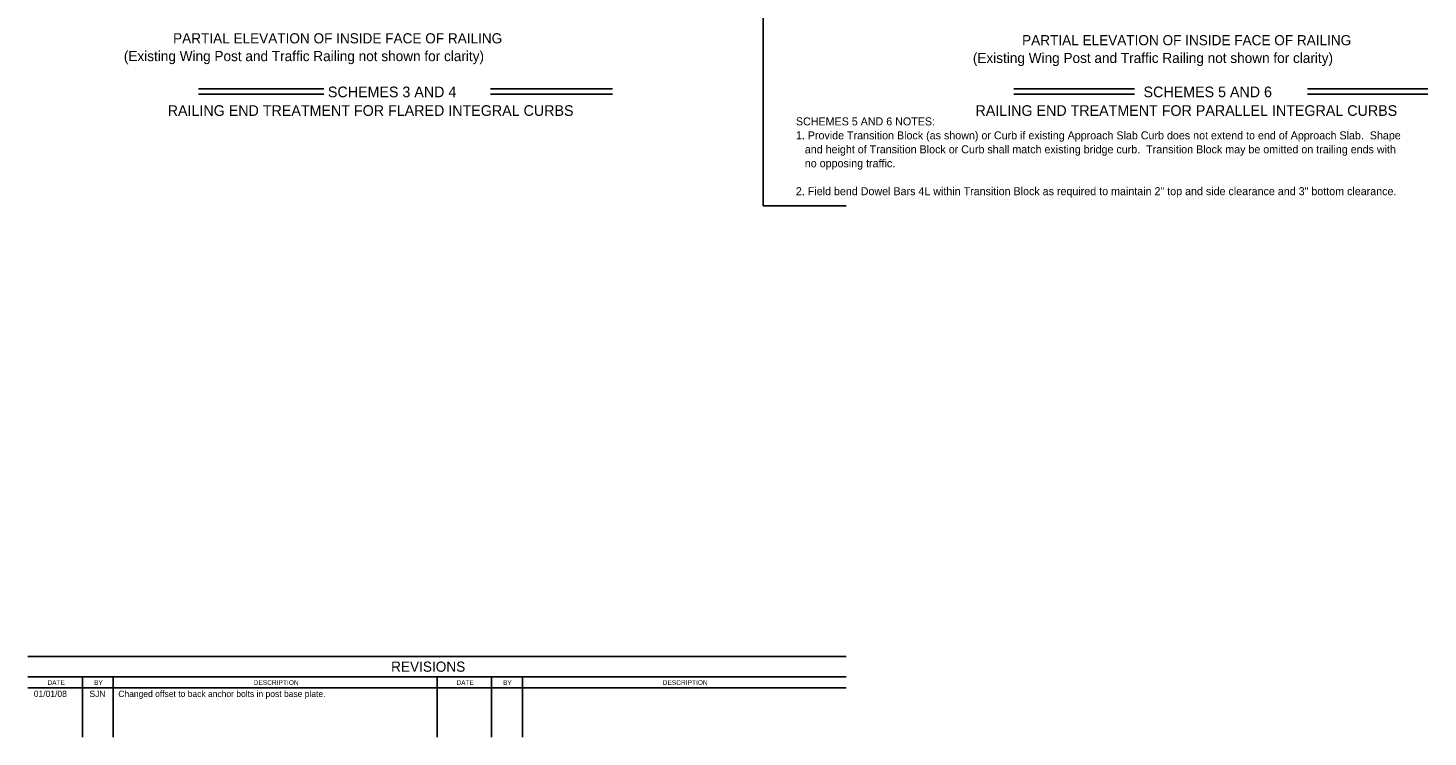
# Model space of a CAD drawing. Extents: x 21587 to 21659.1, y 56113.9 to 56155.9.
# Drawn here: x 21586.98 to 21622.25, y 56113.92 to 56131.8 of the extents above; entities that cross this region are included whole.
import ezdxf

# ---------------------------------------------------------------- set-up
doc = ezdxf.new("R2010")
doc.units = 0
for name, color, linetype in [('Border', 7, 'Continuous'), ('PlotBorder_dp', 7, 'Continuous'), ('SheetBorder_dp', 7, 'Continuous')]:
    doc.layers.add(name, color=color, linetype=linetype)

msp = doc.modelspace()

# ---------------------------------------------------------------- linework, layer by layer
at = {"layer": 'Border'}
for p, q in [((21607.59, 56115.953), (21586.978, 56115.953)), ((21607.59, 56115.438), (21586.978, 56115.438)), ((21588.355, 56115.438), (21588.355, 56113.923)), ((21589.128, 56115.438), (21589.128, 56113.923)), ((21597.284, 56115.438), (21597.284, 56113.923)), ((21598.661, 56115.438), (21598.661, 56113.923)), ((21599.434, 56115.438), (21599.434, 56113.923)), ((21586.978, 56115.165), (21607.59, 56115.165))]:
    msp.add_line(p, q, dxfattribs=at)
at = {"layer": 'PlotBorder_dp'}
for p, q in [((21605.502, 56153.287), (21605.502, 56127.317)), ((21594.432, 56130.27), (21591.272, 56130.27)), ((21598.629, 56130.27), (21601.705, 56130.27)), ((21614.863, 56130.27), (21611.821, 56130.27)), ((21619.217, 56130.27), (21622.254, 56130.27)), ((21594.432, 56130.137), (21591.272, 56130.137)), ((21598.629, 56130.137), (21601.705, 56130.137)), ((21614.863, 56130.137), (21611.821, 56130.137)), ((21619.217, 56130.137), (21622.254, 56130.137)), ((21607.59, 56127.317), (21605.502, 56127.317))]:
    msp.add_line(p, q, dxfattribs=at)

# ---------------------------------------------------------------- texts
at = {"layer": 'Border'}
for s, p in [('SCHEMES 3 AND 4', (21594.535, 56130.057)), ('SCHEMES 5 AND 6', (21615.087, 56130.057)), ('RAILING END TREATMENT FOR FLARED INTEGRAL CURBS', (21590.498, 56129.587)), ('RAILING END TREATMENT FOR PARALLEL INTEGRAL CURBS', (21610.852, 56129.587))]:
    msp.add_text(s, height=0.2688, dxfattribs=at).set_placement(p)
at = {"layer": 'PlotBorder_dp'}
for s, height, p in [('PARTIAL ELEVATION OF INSIDE FACE OF RAILING', 0.256, (21590.634, 56131.415)), ('PARTIAL ELEVATION OF INSIDE FACE OF RAILING', 0.256, (21612.027, 56131.368)), ('(Existing Wing Post and Traffic Railing not shown for clarity)', 0.256, (21589.393, 56130.967)), ('(Existing Wing Post and Traffic Railing not shown for clarity)', 0.256, (21610.786, 56130.92)), ('SCHEMES 5 AND 6 NOTES:', 0.2016, (21606.327, 56129.347)), ('1. Provide Transition Block (as shown) or Curb if existing Approach Slab Curb does not extend to end of Approach Slab.  Shape ', 0.2016, (21606.327, 56128.995)), ('   and height of Transition Block or Curb shall match existing bridge curb.  Transition Block may be omitted on trailing ends with ', 0.2016, (21606.327, 56128.643)), ('   no opposing traffic.', 0.2016, (21606.327, 56128.291)), ('2. Field bend Dowel Bars 4L within Transition Block as required to maintain 2" top and side clearance and 3" bottom clearance.', 0.2016, (21606.327, 56127.587))]:
    msp.add_text(s, height=height, dxfattribs=at).set_placement(p)
at = {"layer": 'SheetBorder_dp'}
for s, height, p in [('REVISIONS', 0.2567, (21596.127, 56115.569)), ('01/01/08', 0.16, (21587.124, 56114.932)), ('SJN', 0.16, (21588.527, 56114.932)), ('BY', 0.1201, (21588.642, 56115.235)), ('Changed offset to back anchor bolts in post base plate.', 0.16, (21589.253, 56114.932)), ('BY', 0.1201, (21598.948, 56115.235))]:
    msp.add_text(s, height=height, dxfattribs=at).set_placement(p)
for s, height, rotation, p in [('DATE', 0.1196, 359.8693, (21587.467, 56115.236)), ('DESCRIPTION', 0.12007, 0.0498, (21592.664, 56115.235)), ('DATE', 0.1196, 359.8693, (21597.773, 56115.236)), ('DESCRIPTION', 0.12007, 0.0498, (21602.971, 56115.235))]:
    msp.add_text(s, height=height, rotation=rotation, dxfattribs=at).set_placement(p)

doc.saveas('drawing.dxf')
